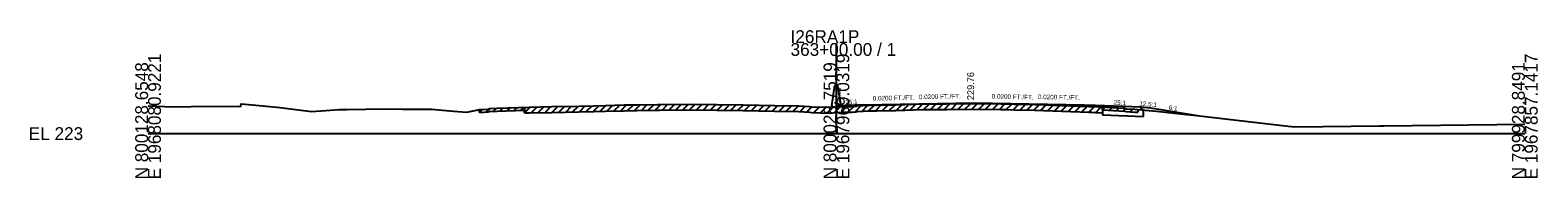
# Model space of a CAD drawing. Extents: x -26 to 304, y -10 to 7527.
# Drawn here: x -25.7 to 302.8, y 6490.3 to 6522.6 of the extents above; entities that cross this region are included whole.
import ezdxf

# ---------------------------------------------------------------- set-up
doc = ezdxf.new("R2010")
doc.units = 0
for name, color, linetype in [('RD_GPK_XS_Cell', 7, 'Continuous'), ('RD_XS_Base', 7, 'Continuous'), ('RD_XS_Box', 7, 'Continuous'), ('RD_XS_EarthShd', 7, 'Continuous'), ('RD_XS_ExGround', 7, 'Continuous'), ('RD_XS_ExPaveRet', 7, 'Continuous'), ('RD_XS_Misc_Line', 7, 'Continuous'), ('RD_XS_Pave', 7, 'Continuous'), ('RD_XS_PaveShd', 7, 'Continuous'), ('RD_XS_TX_Elev_EX', 7, 'Continuous'), ('RD_XS_TX_Elev_PR', 7, 'Continuous'), ('RD_XS_TX_Misc', 7, 'Continuous'), ('RD_XS_TX_MkPT', 7, 'Continuous'), ('RD_XS_TX_Profile', 7, 'Continuous'), ('RD_XS_TX_Station', 7, 'Continuous')]:
    doc.layers.add(name, color=color, linetype=linetype)

msp = doc.modelspace()

# ---------------------------------------------------------------- linework, layer by layer
at = {"layer": 'RD_GPK_XS_Cell'}
for p, q in [((150, 6500), (150, 6519.8)), ((0, 6500), (150, 6500)), ((150, 6500), (300, 6500))]:
    msp.add_line(p, q, dxfattribs=at)
at = {"layer": 'RD_XS_Base'}
for p, q in [((150, 6505.84), (150, 6506.04)), ((216.43, 6505.26), (216.43, 6505.82)), ((216.93, 6505.24), (216.43, 6505.26)), ((216.93, 6503.76), (216.93, 6505.24)), ((208, 6504.12), (216.93, 6503.76))]:
    msp.add_line(p, q, dxfattribs=at)
at = {"layer": 'RD_XS_Box'}
msp.add_line((218.43, 6505.66), (228.68, 6503.96), dxfattribs=at)
at = {"layer": 'RD_XS_EarthShd'}
for p, q in [((149, 6506.06), (149.67, 6510.54)), ((150, 6510.54), (149.67, 6510.54)), ((150, 6510.54), (150.33, 6510.54)), ((151, 6506.06), (150.33, 6510.54)), ((216.43, 6505.82), (218.43, 6505.66))]:
    msp.add_line(p, q, dxfattribs=at)
at = {"layer": 'RD_XS_ExGround'}
msp.add_lwpolyline([(0, 6506.1), (5.48, 6505.88), (9.36, 6505.92), (20.2, 6506), (20.3, 6506.5), (23.45, 6506.21), (28.81, 6505.73), (33.32, 6505.13), (35.59, 6504.82), (37.75, 6504.99), (41.62, 6505.27), (43.3, 6505.3), (51.49, 6505.42), (55.46, 6505.38), (61.74, 6505.35), (66.57, 6504.92), (69.44, 6504.67), (71.21, 6505.08), (72.24, 6505.26), (74.11, 6505.37), (74.4, 6505.5), (76.05, 6505.55), (83.07, 6505.81), (87.95, 6505.9), (93.89, 6506.01), (97.15, 6506.1), (99.68, 6506.16), (103.77, 6506.26), (106.48, 6506.32), (111.01, 6506.38), (111.41, 6506.38), (118.14, 6506.47), (123.96, 6506.39), (129.7, 6506.32), (136.48, 6506.17), (141.82, 6506.05), (144.17, 6505.93), (144.62, 6505.83), (148.42, 6505.75), (150, 6505.84), (151.08, 6505.91), (151.86, 6505.92), (152.9, 6505.92), (153.4, 6505.94), (154.19, 6505.98), (154.42, 6506.07), (157.29, 6506.22), (158.75, 6506.24), (162.51, 6506.3), (162.95, 6506.32), (168.72, 6506.49), (174.08, 6506.54), (180.85, 6506.6), (185.8, 6506.51), (186.89, 6506.5), (188.75, 6506.46), (193.25, 6506.35), (205, 6505.96), (205.62, 6505.94), (206.38, 6505.9), (212.75, 6505.57), (213.15, 6505.42), (215.01, 6505.34), (215.7, 6505.3), (219.73, 6504.89), (224.3, 6504.41), (229.14, 6503.91), (248.46, 6501.63), (249.85, 6501.49), (268.31, 6501.68), (268.77, 6501.68), (269.36, 6501.69), (300, 6502.05)], dxfattribs=at)
at = {"layer": 'RD_XS_ExPaveRet'}
for p, q in [((72.24, 6504.63), (72.24, 6505.26)), ((76.05, 6504.93), (82, 6505.14)), ((82, 6504.52), (82, 6505.77)), ((82, 6505.77), (82, 6505.14)), ((99.68, 6504.91), (103.77, 6505.01)), ((103.77, 6505.01), (106.48, 6505.07)), ((106.48, 6505.07), (111.01, 6505.13)), ((111.01, 6505.13), (111.41, 6505.13)), ((111.41, 6505.13), (118.14, 6505.22)), ((118.14, 6505.22), (123.96, 6505.14)), ((123.96, 6505.14), (129.7, 6505.07)), ((129.7, 6505.07), (136.48, 6504.92)), ((154.42, 6504.82), (157.29, 6504.97)), ((157.29, 6504.97), (158.75, 6504.99)), ((158.75, 6504.99), (162.51, 6505.05)), ((162.51, 6505.05), (162.95, 6505.07)), ((162.95, 6505.07), (168.72, 6505.24)), ((168.72, 6505.24), (174.08, 6505.29)), ((174.08, 6505.29), (180.85, 6505.35)), ((180.85, 6505.35), (185.8, 6505.26)), ((185.8, 6505.26), (186.89, 6505.25)), ((186.89, 6505.25), (188.75, 6505.21)), ((188.75, 6505.21), (193.25, 6505.1)), ((193.25, 6505.1), (205, 6504.71)), ((208, 6505.81), (208, 6504.56)), ((208, 6505.19), (208, 6505.81)), ((208, 6505.19), (212.75, 6504.94)), ((215.7, 6505.3), (215.7, 6504.68)), ((72.24, 6504.63), (74.11, 6504.75)), ((74.11, 6504.75), (74.4, 6504.87)), ((74.4, 6504.87), (76.05, 6504.93)), ((82, 6504.52), (83.07, 6504.56)), ((83.07, 6504.56), (87.95, 6504.65)), ((87.95, 6504.65), (93.89, 6504.76)), ((93.89, 6504.76), (97.15, 6504.85)), ((97.15, 6504.85), (99.68, 6504.91)), ((136.48, 6504.92), (141.82, 6504.8)), ((141.82, 6504.8), (144.17, 6504.68)), ((144.17, 6504.68), (144.62, 6504.58)), ((144.62, 6504.58), (148.42, 6504.5)), ((148.42, 6504.5), (150, 6504.59)), ((150, 6504.59), (151.08, 6504.66)), ((151.08, 6504.66), (151.86, 6504.67)), ((151.86, 6504.67), (152.9, 6504.67)), ((152.9, 6504.67), (153.4, 6504.69)), ((153.4, 6504.69), (154.19, 6504.73)), ((154.19, 6504.73), (154.42, 6504.82)), ((205, 6504.71), (205.62, 6504.69)), ((205.62, 6504.69), (206.38, 6504.65)), ((206.38, 6504.65), (208, 6504.56)), ((212.75, 6504.94), (213.15, 6504.8)), ((213.15, 6504.8), (215.01, 6504.71)), ((215.01, 6504.71), (215.7, 6504.68))]:
    msp.add_line(p, q, dxfattribs=at)
at = {"layer": 'RD_XS_Misc_Line'}
for p, q in [((72.24, 6504.63), (72.91, 6505.3)), ((73.74, 6504.73), (74.52, 6505.5)), ((75.24, 6504.9), (75.89, 6505.55)), ((76.74, 6504.95), (77.39, 6505.6)), ((78.24, 6505.01), (78.89, 6505.66)), ((79.74, 6505.06), (80.39, 6505.71)), ((81.24, 6505.12), (81.89, 6505.76)), ((82, 6504.52), (83.29, 6505.81)), ((83.5, 6504.56), (84.77, 6505.84)), ((85, 6504.59), (86.27, 6505.87)), ((86.5, 6504.62), (87.77, 6505.9)), ((88, 6504.65), (89.27, 6505.92)), ((89.5, 6504.68), (90.77, 6505.95)), ((91, 6504.71), (92.27, 6505.98)), ((92.5, 6504.74), (93.77, 6506.01)), ((94, 6504.77), (95.28, 6506.05)), ((95.5, 6504.8), (96.78, 6506.09)), ((97, 6504.84), (98.28, 6506.12)), ((98.5, 6504.88), (99.78, 6506.16)), ((100, 6504.92), (101.28, 6506.2)), ((101.5, 6504.95), (102.78, 6506.23)), ((103, 6504.99), (104.28, 6506.27)), ((104.5, 6505.02), (105.78, 6506.3)), ((106, 6505.06), (107.27, 6506.33)), ((107.5, 6505.08), (108.77, 6506.35)), ((109, 6505.1), (110.27, 6506.37)), ((110.5, 6505.12), (111.77, 6506.39)), ((112, 6505.14), (113.27, 6506.41)), ((113.5, 6505.16), (114.77, 6506.43)), ((115, 6505.18), (116.27, 6506.45)), ((116.5, 6505.2), (117.77, 6506.47)), ((118, 6505.22), (119.24, 6506.46)), ((119.5, 6505.2), (120.73, 6506.44)), ((121, 6505.18), (122.23, 6506.41)), ((122.5, 6505.16), (123.73, 6506.39)), ((124, 6505.14), (125.24, 6506.37)), ((125.5, 6505.12), (126.74, 6506.36)), ((127, 6505.1), (128.24, 6506.34)), ((128.5, 6505.09), (129.74, 6506.32)), ((130, 6505.07), (131.22, 6506.29)), ((131.5, 6505.03), (132.72, 6506.26)), ((133, 6505), (134.22, 6506.22)), ((134.5, 6504.97), (135.72, 6506.19)), ((136, 6504.93), (137.22, 6506.15)), ((137.5, 6504.9), (138.72, 6506.12)), ((139, 6504.86), (140.22, 6506.08)), ((140.5, 6504.83), (141.72, 6506.05)), ((142, 6504.79), (143.19, 6505.98)), ((143.5, 6504.71), (144.61, 6505.83)), ((145, 6504.57), (146.23, 6505.79)), ((146.5, 6504.54), (147.73, 6505.76)), ((148, 6504.51), (149.29, 6505.8)), ((149.5, 6504.56), (150.83, 6505.89)), ((151, 6504.65), (152.26, 6505.92)), ((152.5, 6504.67), (153.79, 6505.96)), ((154, 6504.72), (155.4, 6506.12)), ((155.5, 6504.87), (156.82, 6506.2)), ((157, 6504.96), (158.28, 6506.24)), ((158.5, 6504.99), (159.77, 6506.26)), ((160, 6505.01), (161.27, 6506.28)), ((161.5, 6505.04), (162.77, 6506.31)), ((163, 6505.07), (164.29, 6506.36)), ((164.5, 6505.11), (165.79, 6506.4)), ((166, 6505.16), (167.29, 6506.45)), ((167.5, 6505.2), (168.79, 6506.49)), ((169, 6505.24), (170.26, 6506.51)), ((170.5, 6505.26), (171.76, 6506.52)), ((172, 6505.27), (173.26, 6506.53)), ((173.5, 6505.28), (174.76, 6506.55)), ((175, 6505.3), (176.26, 6506.56)), ((176.5, 6505.31), (177.76, 6506.57)), ((178, 6505.32), (179.26, 6506.59)), ((179.5, 6505.34), (180.76, 6506.6)), ((181, 6505.35), (182.23, 6506.58)), ((182.5, 6505.32), (183.73, 6506.55)), ((184, 6505.29), (185.23, 6506.52)), ((185.5, 6505.27), (186.73, 6506.5)), ((187, 6505.24), (188.23, 6506.47)), ((188.5, 6505.21), (189.72, 6506.44)), ((190, 6505.18), (191.22, 6506.4)), ((191.5, 6505.15), (192.72, 6506.37)), ((193, 6505.11), (194.21, 6506.32)), ((194.5, 6505.06), (195.71, 6506.27)), ((196, 6505.01), (197.21, 6506.22)), ((197.5, 6504.96), (198.71, 6506.17)), ((199, 6504.91), (200.21, 6506.12)), ((200.5, 6504.86), (201.71, 6506.07)), ((202, 6504.81), (203.21, 6506.02)), ((203.5, 6504.76), (204.71, 6505.97)), ((205, 6504.71), (206.2, 6505.91)), ((206.5, 6504.64), (207.69, 6505.83)), ((208, 6505.19), (208.59, 6505.78)), ((209.5, 6505.11), (210.09, 6505.7)), ((211, 6505.03), (211.6, 6505.63)), ((212.5, 6504.95), (213.02, 6505.47)), ((214, 6504.76), (214.6, 6505.36))]:
    msp.add_line(p, q, dxfattribs=at)
at = {"layer": 'RD_XS_Pave'}
for p, q in [((156, 6506.28), (180, 6506.76)), ((180, 6506.76), (204, 6506.28)), ((204, 6506.28), (206.42, 6506.22))]:
    msp.add_line(p, q, dxfattribs=at)
at = {"layer": 'RD_XS_PaveShd'}
for p, q in [((156, 6506.28), (150, 6506.04)), ((206.42, 6506.22), (216.43, 6505.82))]:
    msp.add_line(p, q, dxfattribs=at)
at = {"layer": 'RD_XS_TX_Elev_PR'}
for p, q in [((150, 6505.84), (151.08, 6505.91)), ((151.08, 6505.91), (151.86, 6505.92)), ((151.86, 6505.92), (152.9, 6505.92)), ((152.9, 6505.92), (153.4, 6505.94)), ((153.4, 6505.94), (154.19, 6505.98)), ((154.19, 6505.98), (154.42, 6506.07)), ((154.42, 6506.07), (157.29, 6506.22)), ((157.29, 6506.22), (158.75, 6506.24)), ((158.75, 6506.24), (162.51, 6506.3)), ((162.51, 6506.3), (162.95, 6506.32)), ((162.95, 6506.32), (168.72, 6506.49)), ((168.72, 6506.49), (174.08, 6506.54)), ((174.08, 6506.54), (180.85, 6506.6)), ((180.85, 6506.6), (185.8, 6506.51)), ((185.8, 6506.51), (186.89, 6506.5)), ((186.89, 6506.5), (188.75, 6506.46)), ((188.75, 6506.46), (193.25, 6506.35)), ((193.25, 6506.35), (205, 6505.96)), ((205, 6505.96), (205.62, 6505.94)), ((205.62, 6505.94), (206.38, 6505.9)), ((206.38, 6505.9), (208, 6505.81)), ((208, 6505.81), (208, 6504.12))]:
    msp.add_line(p, q, dxfattribs=at)

# ---------------------------------------------------------------- texts
at = {"layer": 'RD_GPK_XS_Cell'}
for s, p in [('I26RA1P', (140, 6519.8)), ('363+00.00 / 1', (140, 6517)), ('EL 223', (-26, 6498.6))]:
    msp.add_text(s, height=2.8, dxfattribs=at).set_placement(p)
for s, p in [('N 800128.6548', (0, 6490)), ('E 1968080.9221', (2.8, 6490)), ('N 800028.7519', (150, 6490)), ('E 1967969.0319', (152.8, 6490)), ('N 799928.8491', (300, 6490)), ('E 1967857.1417', (302.8, 6490))]:
    msp.add_text(s, height=2.8, rotation=90, dxfattribs=at).set_placement(p)
at = {"layer": 'RD_XS_TX_Elev_EX'}
msp.add_text('228.84', height=1, rotation=90, dxfattribs=at).set_placement((151, 6505.84))
at = {"layer": 'RD_XS_TX_Misc'}
msp.add_text('12.5:1', height=1, rotation=355.4297, dxfattribs=at).set_placement((215.97, 6506.11))
at = {"layer": 'RD_XS_TX_MkPT'}
for rotation, p in [(2.2906, (151.94, 6506.37)), (357.7112, (210.38, 6506.31))]:
    msp.add_text('25:1', height=1, rotation=rotation, dxfattribs=at).set_placement(p)
at = {"layer": 'RD_XS_TX_Profile'}
for s, rotation, p in [('0.0200 FT./FT.', 1.1458, (157.92, 6507.21)), ('0.0200 FT./FT.', 1.1458, (167.98, 6507.52)), ('0.0200 FT./FT.', 358.569, (183.84, 6507.67)), ('0.0200 FT./FT.', 358.8542, (193.89, 6507.56)), ('6:1', 350.5451, (222.35, 6505.25))]:
    msp.add_text(s, height=1, rotation=rotation, dxfattribs=at).set_placement(p)
at = {"layer": 'RD_XS_TX_Station'}
msp.add_text(' 229.76', height=1.5, rotation=90, dxfattribs=at).set_placement((180, 6506.76))

doc.saveas('drawing.dxf')
